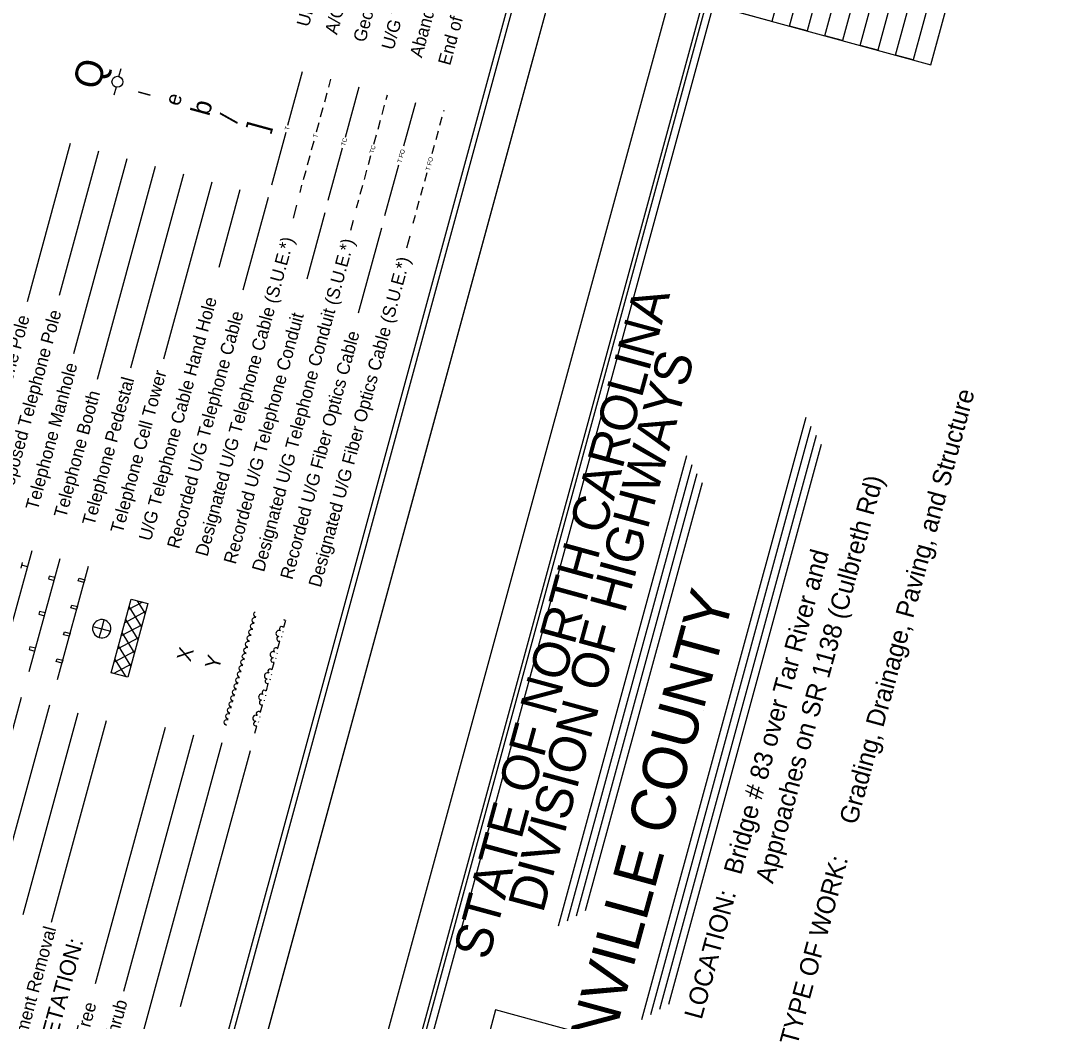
# Model space of a CAD drawing. Extents: x 2076126 to 2079903, y 925480 to 928006.
# Drawn here: x 2078320 to 2079033, y 926403 to 927085 of the extents above; entities that cross this region are included whole.
import ezdxf

# ---------------------------------------------------------------- set-up
doc = ezdxf.new("R2010")
doc.units = 0
for name, color, linetype in [('Default', 7, 'Continuous'), ('Sheet Cutting Line CELL', 7, 'Continuous'), ('Sheet Data Field CELL', 7, 'Continuous'), ('Sheet Plot Border Inside CELL', 7, 'Continuous'), ('Sheet Plot Border Outside CELL', 7, 'Continuous'), ('Sheet Symbology CELL', 7, 'Continuous'), ('Sheet Title CELL', 7, 'Continuous'), ('Sheet Title Data Points CELL', 7, 'Continuous')]:
    doc.layers.add(name, color=color, linetype=linetype)

msp = doc.modelspace()

# ---------------------------------------------------------------- linework, layer by layer
at = {"layer": 'Default'}
for p, q in [((2078643.24, 926410.74), (2078526.08, 925981.22)), ((2078934.09, 926331.41), (2078643.24, 926410.74))]:
    msp.add_line(p, q, dxfattribs=at)
at = {"layer": 'Sheet Cutting Line CELL'}
msp.add_line((2078321.04, 925784.51), (2078764.17, 927409.16), dxfattribs=at)
at = {"layer": 'Sheet Plot Border Inside CELL'}
for points in [[(2078302.8, 925802.96), (2078741.33, 927410.72), (2077723.41, 927688.37), (2077284.89, 926080.6)], [(2079441.8, 925498.58), (2079880.32, 927106.35), (2078862.41, 927383.99), (2078423.88, 925776.22)]]:
    msp.add_lwpolyline(points, close=True, dxfattribs=at)
at = {"layer": 'Sheet Plot Border Outside CELL'}
for points in [[(2078321.04, 925784.51), (2078764.17, 927409.16), (2077702.94, 927698.61), (2077259.81, 926073.96)], [(2078841.94, 927394.24), (2078398.8, 925769.59), (2079460.02, 925480.14), (2079903.16, 927104.79)]]:
    msp.add_lwpolyline(points, close=True, dxfattribs=at)
at = {"layer": 'Sheet Symbology CELL'}
for p, q in [((2078386.36, 927047.43), (2078387.84, 927052.85)), ((2078501.68, 927014.25), (2078511.65, 927050.79)), ((2078384.39, 927040.19), (2078382.91, 927034.76)), ((2078529.48, 927040.15), (2078530.95, 927045.53)), ((2078540.92, 927006.1), (2078550.24, 927040.26)), ((2078526.72, 927030.02), (2078528.43, 927036.29)), ((2078568.64, 927031.71), (2078569.54, 927035)), ((2078523.95, 927019.89), (2078525.66, 927026.16)), ((2078565.87, 927021.58), (2078567.59, 927027.85)), ((2078580.77, 927000.19), (2078588.83, 927029.74)), ((2078563.11, 927011.45), (2078564.82, 927017.72)), ((2078605.32, 927014.19), (2078606.9, 927019.98)), ((2078607.95, 927023.84), (2078608.13, 927024.47)), ((2078521.19, 927009.76), (2078522.9, 927016.03)), ((2078490.6, 926973.61), (2078500.37, 927009.42)), ((2078517.8, 926997.31), (2078519.51, 927003.58)), ((2078560.35, 927001.32), (2078562.06, 927007.59)), ((2078602.69, 927004.54), (2078604.27, 927010.33)), ((2078353.16, 927001.75), (2078323.72, 926893.81)), ((2078372.46, 926996.49), (2078345.6, 926898.02)), ((2078529.19, 926963.08), (2078538.95, 926998.86)), ((2078600.06, 926994.89), (2078601.64, 927000.68)), ((2078391.75, 926991.23), (2078355.47, 926858.22)), ((2078515.03, 926987.18), (2078516.74, 926993.45)), ((2078556.53, 926987.33), (2078558.24, 926993.6)), ((2078411.05, 926985.96), (2078371.44, 926840.77)), ((2078512.27, 926977.05), (2078513.98, 926983.32)), ((2078553.77, 926977.2), (2078555.48, 926983.47)), ((2078567.78, 926952.56), (2078577.22, 926987.17)), ((2078430.34, 926980.7), (2078394.25, 926848.37)), ((2078449.64, 926975.44), (2078416.69, 926854.63)), ((2078594.93, 926976.08), (2078596.51, 926981.87)), ((2078468.93, 926970.18), (2078454.45, 926917.08)), ((2078509.89, 926968.35), (2078511.22, 926973.19)), ((2078551.01, 926967.07), (2078552.72, 926973.34)), ((2078592.29, 926966.43), (2078593.87, 926972.22)), ((2078488.23, 926964.91), (2078470.98, 926901.66)), ((2078548.48, 926957.82), (2078549.95, 926963.21)), ((2078589.66, 926956.78), (2078591.24, 926962.57)), ((2078507.52, 926959.65), (2078505.12, 926950.84)), ((2078526.82, 926954.39), (2078514.47, 926909.12)), ((2078546.11, 926949.12), (2078544.25, 926942.31)), ((2078587.07, 926947.29), (2078588.61, 926952.93)), ((2078565.41, 926943.86), (2078549.61, 926885.95)), ((2078584.7, 926938.6), (2078582.45, 926930.34)), ((2078326.95, 926723.9), (2078305.9, 926646.72)), ((2078325.19, 926641.46), (2078346.24, 926718.64)), ((2078319.65, 926712.13), (2078320.7, 926715.99)), ((2078323.98, 926713.02), (2078320.17, 926714.06)), ((2078344.49, 926636.19), (2078365.54, 926713.37)), ((2078381.09, 926640.67), (2078394.8, 926690.93)), ((2078394.8, 926690.93), (2078406.09, 926687.85)), ((2078404.29, 926681.25), (2078399.05, 926689.78)), ((2078404.59, 926682.36), (2078390.4, 926674.77)), ((2078406.09, 926687.85), (2078392.38, 926637.59)), ((2078402.47, 926688.84), (2078392.84, 926683.75)), ((2078401.85, 926672.32), (2078393.45, 926685.96)), ((2078374.64, 926670.7), (2078376.29, 926676.73)), ((2078399.41, 926663.35), (2078391.01, 926677.04)), ((2078477.25, 926676.63), (2078477.5, 926677.55)), ((2078477.48, 926675.74), (2078477.25, 926676.63)), ((2078477.95, 926674.99), (2078477.48, 926675.74)), ((2078477.5, 926677.55), (2078478.2, 926678.19)), ((2078478.2, 926678.19), (2078478.97, 926678.55)), ((2078478.37, 926680.73), (2078478.62, 926681.65)), ((2078478.59, 926679.84), (2078478.37, 926680.73)), ((2078479.06, 926679.09), (2078478.59, 926679.84)), ((2078478.62, 926681.65), (2078479.31, 926682.29)), ((2078478.97, 926678.55), (2078479.84, 926678.52)), ((2078479.9, 926678.55), (2078479.06, 926679.09)), ((2078479.31, 926682.29), (2078479.38, 926682.33)), ((2078498.8, 926671.84), (2078500.12, 926676.67)), ((2078368.61, 926672.34), (2078374.64, 926670.7)), ((2078373, 926664.67), (2078374.64, 926670.7)), ((2078374.64, 926670.7), (2078380.67, 926669.06)), ((2078402.14, 926673.38), (2078387.96, 926665.85)), ((2078396.96, 926654.38), (2078388.58, 926668.12)), ((2078475.02, 926668.43), (2078475.27, 926669.35)), ((2078475.24, 926667.54), (2078475.02, 926668.43)), ((2078475.27, 926669.35), (2078475.96, 926669.99)), ((2078475.96, 926669.99), (2078476.73, 926670.35)), ((2078476.13, 926672.53), (2078476.38, 926673.45)), ((2078476.36, 926671.64), (2078476.13, 926672.53)), ((2078476.83, 926670.89), (2078476.36, 926671.64)), ((2078476.38, 926673.45), (2078477.08, 926674.09)), ((2078476.73, 926670.35), (2078477.6, 926670.32)), ((2078477.66, 926670.35), (2078476.83, 926670.89)), ((2078477.08, 926674.09), (2078477.85, 926674.45)), ((2078477.85, 926674.45), (2078478.72, 926674.42)), ((2078478.78, 926674.45), (2078477.95, 926674.99)), ((2078498.35, 926668.29), (2078498.48, 926668.77)), ((2078399.7, 926664.41), (2078385.53, 926656.93)), ((2078472.78, 926660.23), (2078473.03, 926661.15)), ((2078473.03, 926661.15), (2078473.72, 926661.79)), ((2078473.72, 926661.79), (2078474.49, 926662.15)), ((2078473.9, 926664.33), (2078474.15, 926665.25)), ((2078474.12, 926663.44), (2078473.9, 926664.33)), ((2078474.59, 926662.69), (2078474.12, 926663.44)), ((2078474.15, 926665.25), (2078474.84, 926665.89)), ((2078474.49, 926662.15), (2078475.37, 926662.12)), ((2078475.43, 926662.15), (2078474.59, 926662.69)), ((2078474.84, 926665.89), (2078475.61, 926666.25)), ((2078475.71, 926666.79), (2078475.24, 926667.54)), ((2078475.61, 926666.25), (2078476.49, 926666.22)), ((2078476.55, 926666.25), (2078475.71, 926666.79)), ((2078494.85, 926657.37), (2078496.17, 926662.2)), ((2078497.43, 926664.91), (2078497.56, 926665.39)), ((2078397.26, 926655.49), (2078383.08, 926647.95)), ((2078394.53, 926645.45), (2078386.13, 926659.14)), ((2078471.49, 926653.59), (2078472.26, 926653.95)), ((2078471.66, 926656.13), (2078471.91, 926657.05)), ((2078471.88, 926655.24), (2078471.66, 926656.13)), ((2078472.35, 926654.49), (2078471.88, 926655.24)), ((2078471.91, 926657.05), (2078472.6, 926657.69)), ((2078472.26, 926653.95), (2078473.13, 926653.92)), ((2078473.19, 926653.95), (2078472.35, 926654.49)), ((2078472.6, 926657.69), (2078473.38, 926658.05)), ((2078473, 926659.34), (2078472.78, 926660.23)), ((2078473.47, 926658.59), (2078473, 926659.34)), ((2078473.38, 926658.05), (2078474.25, 926658.02)), ((2078474.31, 926658.05), (2078473.47, 926658.59)), ((2078494.4, 926653.82), (2078494.53, 926654.3)), ((2078391.27, 926637.89), (2078383.69, 926650.17)), ((2078469.42, 926647.93), (2078469.67, 926648.85)), ((2078469.65, 926647.04), (2078469.42, 926647.93)), ((2078470.12, 926646.29), (2078469.65, 926647.04)), ((2078469.67, 926648.85), (2078470.37, 926649.49)), ((2078470.37, 926649.49), (2078471.14, 926649.85)), ((2078470.54, 926652.03), (2078470.79, 926652.95)), ((2078470.77, 926651.14), (2078470.54, 926652.03)), ((2078471.24, 926650.39), (2078470.77, 926651.14)), ((2078470.79, 926652.95), (2078471.49, 926653.59)), ((2078471.14, 926649.85), (2078472.01, 926649.82)), ((2078472.07, 926649.85), (2078471.24, 926650.39)), ((2078490.91, 926642.9), (2078492.22, 926647.73)), ((2078493.48, 926650.44), (2078493.61, 926650.92)), ((2078392.38, 926637.59), (2078381.09, 926640.67)), ((2078381.67, 926640.51), (2078381.24, 926641.2)), ((2078394.82, 926646.51), (2078382.83, 926640.2)), ((2078467.19, 926639.73), (2078467.44, 926640.65)), ((2078467.41, 926638.84), (2078467.19, 926639.73)), ((2078467.44, 926640.65), (2078468.13, 926641.29)), ((2078468.13, 926641.29), (2078468.9, 926641.65)), ((2078468.31, 926643.83), (2078468.56, 926644.75)), ((2078468.53, 926642.94), (2078468.31, 926643.83)), ((2078469, 926642.19), (2078468.53, 926642.94)), ((2078468.56, 926644.75), (2078469.25, 926645.39)), ((2078468.9, 926641.65), (2078469.77, 926641.62)), ((2078469.84, 926641.65), (2078469, 926642.19)), ((2078469.25, 926645.39), (2078470.02, 926645.75)), ((2078470.02, 926645.75), (2078470.89, 926645.72)), ((2078470.95, 926645.75), (2078470.12, 926646.29)), ((2078490.46, 926639.34), (2078490.59, 926639.83)), ((2078464.95, 926631.53), (2078465.2, 926632.45)), ((2078465.2, 926632.45), (2078465.89, 926633.09)), ((2078465.89, 926633.09), (2078466.67, 926633.45)), ((2078466.07, 926635.63), (2078466.32, 926636.55)), ((2078466.29, 926634.74), (2078466.07, 926635.63)), ((2078466.76, 926633.99), (2078466.29, 926634.74)), ((2078466.32, 926636.55), (2078467.01, 926637.19)), ((2078466.67, 926633.45), (2078467.54, 926633.42)), ((2078467.6, 926633.45), (2078466.76, 926633.99)), ((2078467.01, 926637.19), (2078467.78, 926637.55)), ((2078467.88, 926638.09), (2078467.41, 926638.84)), ((2078467.78, 926637.55), (2078468.66, 926637.52)), ((2078468.72, 926637.55), (2078467.88, 926638.09)), ((2078486.96, 926628.43), (2078488.28, 926633.25)), ((2078489.53, 926635.97), (2078489.67, 926636.45)), ((2078463.83, 926627.43), (2078464.08, 926628.35)), ((2078464.06, 926626.54), (2078463.83, 926627.43)), ((2078464.53, 926625.79), (2078464.06, 926626.54)), ((2078464.08, 926628.35), (2078464.78, 926628.99)), ((2078465.36, 926625.25), (2078464.53, 926625.79)), ((2078464.78, 926628.99), (2078465.55, 926629.35)), ((2078465.17, 926630.64), (2078464.95, 926631.53)), ((2078465.64, 926629.89), (2078465.17, 926630.64)), ((2078465.55, 926629.35), (2078466.42, 926629.32)), ((2078466.48, 926629.35), (2078465.64, 926629.89)), ((2078486.51, 926624.87), (2078486.64, 926625.36)), ((2078319.76, 926623.73), (2078292.32, 926523.11)), ((2078339.06, 926618.47), (2078311.61, 926517.84)), ((2078461.6, 926619.23), (2078461.85, 926620.15)), ((2078461.82, 926618.34), (2078461.6, 926619.23)), ((2078462.29, 926617.59), (2078461.82, 926618.34)), ((2078461.85, 926620.15), (2078462.54, 926620.79)), ((2078462.54, 926620.79), (2078463.31, 926621.15)), ((2078462.71, 926623.33), (2078462.96, 926624.25)), ((2078462.94, 926622.44), (2078462.71, 926623.33)), ((2078463.41, 926621.69), (2078462.94, 926622.44)), ((2078462.96, 926624.25), (2078463.66, 926624.89)), ((2078463.31, 926621.15), (2078464.18, 926621.12)), ((2078464.24, 926621.15), (2078463.41, 926621.69)), ((2078463.66, 926624.89), (2078464.43, 926625.25)), ((2078464.43, 926625.25), (2078465.3, 926625.22)), ((2078483.01, 926613.96), (2078484.33, 926618.78)), ((2078485.59, 926621.5), (2078485.72, 926621.98)), ((2078358.35, 926613.21), (2078320.82, 926475.61)), ((2078459.36, 926611.03), (2078459.61, 926611.95)), ((2078459.58, 926610.14), (2078459.36, 926611.03)), ((2078459.61, 926611.95), (2078460.3, 926612.59)), ((2078460.3, 926612.59), (2078461.07, 926612.95)), ((2078460.48, 926615.13), (2078460.73, 926616.05)), ((2078460.7, 926614.24), (2078460.48, 926615.13)), ((2078461.17, 926613.49), (2078460.7, 926614.24)), ((2078460.73, 926616.05), (2078461.42, 926616.69)), ((2078461.07, 926612.95), (2078461.95, 926612.92)), ((2078462.01, 926612.95), (2078461.17, 926613.49)), ((2078461.42, 926616.69), (2078462.19, 926617.05)), ((2078462.19, 926617.05), (2078463.06, 926617.02)), ((2078463.13, 926617.05), (2078462.29, 926617.59)), ((2078377.65, 926607.94), (2078340.12, 926470.34)), ((2078458.24, 926606.93), (2078458.49, 926607.85)), ((2078458.46, 926606.04), (2078458.24, 926606.93)), ((2078458.93, 926605.29), (2078458.46, 926606.04)), ((2078458.49, 926607.85), (2078459.18, 926608.49)), ((2078459.77, 926604.75), (2078458.93, 926605.29)), ((2078459.18, 926608.49), (2078459.96, 926608.85)), ((2078460.05, 926609.39), (2078459.58, 926610.14)), ((2078459.96, 926608.85), (2078460.83, 926608.82)), ((2078460.89, 926608.85), (2078460.05, 926609.39)), ((2078479.07, 926599.49), (2078480.38, 926604.31)), ((2078481.64, 926607.03), (2078481.77, 926607.51)), ((2078482.56, 926610.4), (2078482.69, 926610.88)), ((2078417.92, 926603.32), (2078370.26, 926428.58)), ((2078437.21, 926598.06), (2078389.55, 926423.32)), ((2078456.51, 926592.79), (2078400.54, 926387.6)), ((2078475.81, 926587.53), (2078428.14, 926412.79))]:
    msp.add_line(p, q, dxfattribs=at)
for points in [[(2077722.58, 927675.63), (2077327.87, 926228.5), (2078339.88, 925952.47), (2078734.6, 927399.6)], [(2078342.16, 926703.66), (2078342.69, 926705.59), (2078338.83, 926706.64), (2078338.3, 926704.71)], [(2078358.64, 926703.3), (2078359.17, 926705.23), (2078363.03, 926704.17), (2078362.5, 926702.24)], [(2078335.58, 926679.54), (2078336.11, 926681.47), (2078332.25, 926682.52), (2078331.72, 926680.59)], [(2078353.64, 926684.97), (2078354.17, 926686.9), (2078358.03, 926685.84), (2078357.5, 926683.91)], [(2078348.65, 926666.64), (2078349.17, 926668.57), (2078353.03, 926667.51), (2078352.5, 926665.58)], [(2078329, 926655.42), (2078329.53, 926657.35), (2078325.67, 926658.4), (2078325.14, 926656.47)], [(2078343.65, 926648.31), (2078344.17, 926650.23), (2078348.03, 926649.18), (2078347.5, 926647.25)]]:
    msp.add_lwpolyline(points, close=True, dxfattribs=at)
msp.add_circle((2078385.35, 927043.78), 3.75, dxfattribs=at)
for centre, radius, start, end in [((2078374.64, 926670.7), 6.25, 74.73779, 164.74233), ((2078374.64, 926670.7), 6.25, 344.73779, 74.74233), ((2078499.52, 926678.33), 1.58, 230.99442, 278.49239), ((2078374.64, 926670.7), 6.25, 164.73779, 254.74233), ((2078374.64, 926670.7), 6.25, 254.73779, 344.74233), ((2078495.53, 926667.5), 2.06, 60.70716, 268.77965), ((2078497.41, 926670.61), 1.58, 35.51188, 236.30845), ((2078495.57, 926663.86), 1.58, 93.17835, 293.97492), ((2078491.58, 926653.03), 2.06, 60.70716, 268.77965), ((2078493.47, 926656.14), 1.58, 35.51188, 236.30845), ((2078491.62, 926649.39), 1.58, 93.17835, 293.97492), ((2078487.63, 926638.56), 2.06, 60.70716, 268.77965), ((2078489.52, 926641.67), 1.58, 35.51188, 236.30845), ((2078487.68, 926634.92), 1.58, 93.17835, 293.97492), ((2078483.69, 926624.09), 2.06, 60.70716, 268.77965), ((2078485.57, 926627.2), 1.58, 35.51188, 236.30845), ((2078483.73, 926620.45), 1.58, 93.17835, 293.97492), ((2078479.74, 926609.62), 2.06, 60.70716, 268.77965), ((2078481.63, 926612.73), 1.58, 35.51188, 236.30845), ((2078479.78, 926605.98), 1.58, 93.17835, 293.97492)]:
    msp.add_arc(centre, radius, start, end, dxfattribs=at)
at = {"layer": 'Sheet Title CELL'}
for p, q in [((2078743.04, 926404.12), (2078855.15, 926815.1)), ((2078749.18, 926407.63), (2078858.66, 926808.96)), ((2078755.34, 926411.13), (2078862.16, 926802.83)), ((2078761.46, 926414.64), (2078865.68, 926796.68)), ((2078686.26, 926467.96), (2078773.8, 926788.99)), ((2078692.38, 926471.47), (2078777.32, 926782.85)), ((2078698.53, 926474.98), (2078780.82, 926776.71)), ((2078704.67, 926478.49), (2078784.33, 926770.57))]:
    msp.add_line(p, q, dxfattribs=at)
for points in [[(2078858.95, 927361.63), (2078469.48, 925933.76)], [(2078862.46, 927355.47), (2078488.8, 925985.53)], [(2078904.06, 927350.35), (2078831.7, 927085.04), (2078807.58, 927091.62)], [(2078928.19, 927343.76), (2078855.83, 927078.46), (2078843.77, 927081.74), (2078916.13, 927347.05)], [(2078952.3, 927337.19), (2078879.94, 927071.88), (2078867.89, 927075.17), (2078940.24, 927340.48)], [(2078976.43, 927330.61), (2078904.07, 927065.31), (2078891.99, 927068.59), (2078964.36, 927333.9)], [(2079000.55, 927324.03), (2078928.17, 927058.72), (2078916.13, 927062.01), (2078988.49, 927327.32)], [(2078940.23, 927055.43), (2079012.6, 927320.74)], [(2078795.53, 927094.9), (2078940.23, 927055.43), (2078964.36, 927143.85)]]:
    msp.add_lwpolyline(points, dxfattribs=at)
at = {"layer": 'Sheet Title Data Points CELL'}
for p, q in [((2078869.16, 926716.54), (2078869.16, 926716.54)), ((2078785.13, 926615.03), (2078785.13, 926615.03))]:
    msp.add_line(p, q, dxfattribs=at)

# ---------------------------------------------------------------- texts
at = {"layer": 'Sheet Data Field CELL'}
for s, height, p in [('Grading, Drainage, Paving, and Structure', 12.5001, (2078889.53, 926536.49)), ('Approaches on SR 1138 (Culbreth Rd)', 12.5001, (2078832.4, 926496.32)), ('Bridge # 83 over Tar River and          ', 12.5001, (2078810.7, 926502.24)), ('       GRANVILLE COUNTY      ', 30, (2078678.87, 926225.47))]:
    msp.add_text(s, height=height, rotation=74.7434, dxfattribs=at).set_placement(p)
at = {"layer": 'Sheet Symbology CELL'}
for s, height, p in [('Underground Storage Tank, Approx. Loc.', 8.75, (2078515.79, 927080.78)), ('Abandoned According to Utility Records', 8.75, (2078592.97, 927059.73)), ('A/G Tank; Water, Gas, Oil', 8.75, (2078535.09, 927075.52)), ('Geoenvironmental Boring', 8.75, (2078554.38, 927070.25)), ('U/G Test Hole (S.U.E.*)', 8.75, (2078573.68, 927064.99)), ('End of Information', 8.75, (2078612.27, 927054.47)), ('Q', 18.75, (2078372.64, 927037.53)), ('l', 8.25, (2078407.54, 927033.45)), ('e', 10.5, (2078427.63, 927026.8)), ('b', 13.2, (2078447.87, 927019.88)), ('/', 12.5, (2078466.92, 927015.05)), (']', 13.5, (2078486.57, 927009.17)), ('T', 3, (2078502.22, 927010.53)), ('T', 3, (2078521.54, 927005.36)), ('TC', 3, (2078540.75, 926999.77)), ('TC', 3, (2078560.11, 926994.75)), ('T FO', 3, (2078579.06, 926988.22)), ('T FO', 3, (2078598.35, 926982.92)), ('Designated U/G Telephone Cable (S.U.E.*)', 8.75, (2078446.72, 926719.49)), ('Designated U/G Telephone Conduit (S.U.E.*)', 8.75, (2078485.31, 926708.96)), ('Designated U/G Fiber Optics Cable (S.U.E.*)', 8.75, (2078523.9, 926698.43)), ('U/G Telephone Cable Hand Hole', 8.75, (2078408.13, 926730.01)), ('Existing Telephone Pole', 8.75, (2078292.36, 926761.58)), ('Proposed Telephone Pole', 8.75, (2078311.65, 926756.31)), ('Recorded U/G Telephone Cable', 8.75, (2078427.42, 926724.75)), ('Recorded U/G Telephone Conduit', 8.75, (2078466.01, 926714.22)), ('Recorded U/G Fiber Optics Cable', 8.75, (2078504.61, 926703.7)), ('Telephone Manhole', 8.75, (2078330.95, 926751.05)), ('Telephone Cell Tower', 8.75, (2078388.83, 926735.27)), ('Telephone Pedestal', 8.75, (2078369.54, 926740.53)), ('Telephone Booth', 8.75, (2078350.24, 926745.79)), ('X', 10, (2078435.21, 926647.73)), ('Y', 10, (2078454.51, 926642.46)), ('Pavement Removal', 8.75, (2078316.83, 926367.74)), ('VEGETATION:', 11, (2078336.21, 926362.45)), ('Single Tree', 8.75, (2078355.4, 926356.92)), ('Single Shrub', 8.75, (2078374.7, 926351.66))]:
    msp.add_text(s, height=height, rotation=74.7434, dxfattribs=at).set_placement(p)
at = {"layer": 'Sheet Title CELL'}
for s, height, p in [('STATE OF NORTH CAROLINA', 24.9999, (2078638.29, 926443.94)), ('DIVISION OF HIGHWAYS', 24.9999, (2078675.57, 926476.16)), ('TYPE OF WORK:', 12.5001, (2078848.92, 926385.81)), ('LOCATION: ', 12.5, (2078783.79, 926403.58))]:
    msp.add_text(s, height=height, rotation=74.7434, dxfattribs=at).set_placement(p)

doc.saveas('drawing.dxf')
